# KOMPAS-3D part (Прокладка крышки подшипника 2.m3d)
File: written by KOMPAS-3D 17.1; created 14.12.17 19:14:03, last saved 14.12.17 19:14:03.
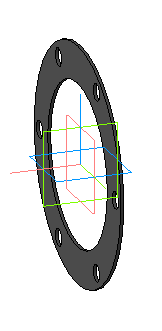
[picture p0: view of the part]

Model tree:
1. Операция без истории:1  (labels: Прокладка крышки подшипника 2)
